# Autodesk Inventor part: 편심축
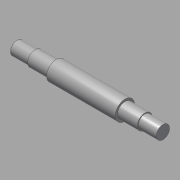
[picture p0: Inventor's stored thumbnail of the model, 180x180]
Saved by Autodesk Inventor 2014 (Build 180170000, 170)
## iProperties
Created: 2015-10
Part Number: 편심축
Document SubType Name: Modeling
Designer: mdu
Density: 7.86 g/cm^3
Material: 강철, 연강
Mass: 1163.82 g
Surface Area: 210.981 cm^2
Volume: 148.069 cm^3
Appearance: Steel
Author: mdu
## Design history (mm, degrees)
sketch "스케치1"
  geometry: L1 (-20.5, -41.331)-(-20.5, 32.669) reference; L2 (7.5, -30.031)-(7.5, 21.369) reference; L3 (135.5, -30.331)-(135.5, 21.669) reference; L4 (121.5, 21.369)-(121.5, -30.031) reference; L5 (184.5, -4.331)-(-7.5, -4.331); L6 (184.5, -4.331)-(184.5, 6.669); L7 (154.5, 8.169)-(121.5, 8.169); L8 (121.5, 8.169)-(121.5, 11.669); L9 (121.5, 11.669)-(7.5, 11.669); L10 (7.5, 11.669)-(7.5, 8.169); L11 (7.5, 8.169)-(-7.5, 8.169); L12 (-7.5, 8.169)-(-7.5, -4.331); L13 (154.5, 8.169)-(154.5, 6.669); L14 (154.5, 6.669)-(184.5, 6.669); C1 r 32.5 at (64.5, -4.331) reference; 1 further point
  constraints: 21 end point, 8 perpendicular, 5 point on line, 1 collinear
  dimensions: "d1" = 25 diameter of L11 L5; "d2" = 32 diameter of L9 L5; "d4" = 15 distance of L10.end L11.end; "d15" = 33 distance of L7.start L7.end; "d26" = 30 distance of L13.end L6.end; "d36" = 22 diameter of L14 L5
revolve "회전1" sketch "스케치1" stored, may be unused: angle "d6" = 90 deg
node "작업 평면1"
sketch "스케치2"
  geometry: C1 r 16 at (0, 0) reference; C2 r 20.75 at (0, 4)
  constraints: 1 centre point, 1 vertical alignment
  dimensions: "d34" = 4 distance of C2.centre C1.centre; "d35" = 41.5 diameter of C2
extrude "돌출1" join sketch "스케치2" stored distance "d9" = 40; taper "d10" = 0 deg
chamfer "모따기1" distance "d11" = 1; stored, may be unused: second distance "d12" = 2, angle "d13" = 45 deg
node "작업 평면2"
sketch "스케치3"
  geometry: L1 (-15, -10)-(-15, 10) reference; L2 (-15, 3)-(0, 3); L3 (0, -3)-(-15, -3); A1 r 3 centre (0, 0) between (0, -3) and (0, 3); 2 further points
  constraints: 4 end point, 2 perpendicular, 2 point on circle, 2 point on line, 2 tangent, 1 centre point, 1 horizontal alignment, 1 midpoint
  dimensions: "d16" = 18 dimension on A1 L1; "d17" = 6 distance between parallel lines of L3 L2
extrude "돌출2" cut sketch "스케치3" distance "d18" = 3.5; taper "d19" = 0 deg
node "솔리드1"
node "참조1"
node "참조2"
node "참조3"
node "참조4"
node "참조5"
other parameters: "d30" = 35
